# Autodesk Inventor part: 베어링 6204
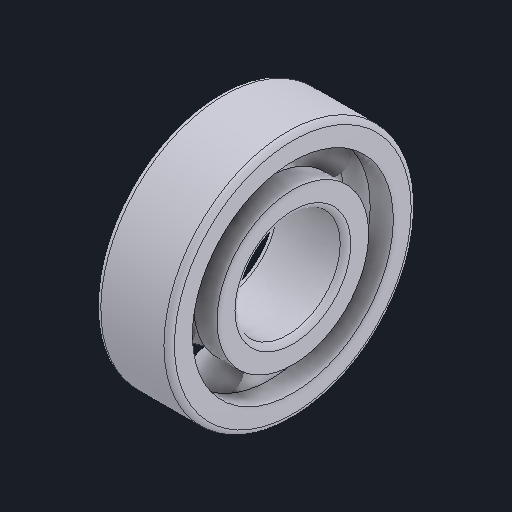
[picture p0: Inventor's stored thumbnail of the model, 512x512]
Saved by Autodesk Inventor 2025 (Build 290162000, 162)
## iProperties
Created: 2025-08
Part Number: 베어링 6204
Material: 강철, 연강
Description: 깊은 그루브 볼 베어링
Document SubType Name: Modeling
Designer: infra08
Density: 7.86 g/cm^3
Appearance: 기본값
Author: jhkim
Sending System: Autodesk Inventor 2026
Preprocessor: ST-DEVELOPER v20.1
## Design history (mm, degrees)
feature "Solid1"
feature "Solid1:1"
feature "Solid1:2"
feature "Solid1:3"
feature "Solid1:4"
feature "Solid1:5"
feature "Solid1:6"
feature "Solid1:7"
feature "Solid1:8"
node "솔리드1"
node "솔리드2"
node "솔리드3"
node "솔리드4"
node "솔리드5"
node "솔리드6"
node "솔리드7"
node "솔리드8"
node "솔리드9"
